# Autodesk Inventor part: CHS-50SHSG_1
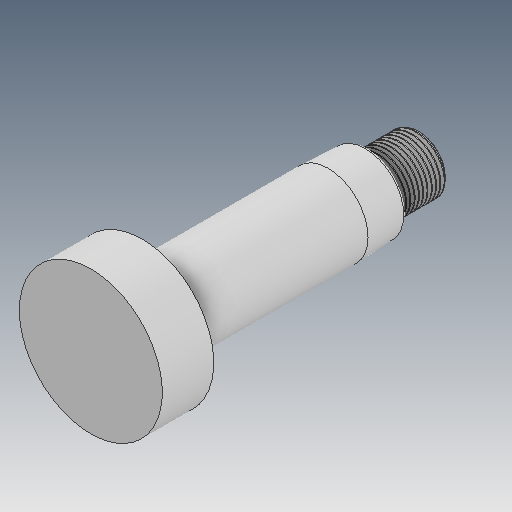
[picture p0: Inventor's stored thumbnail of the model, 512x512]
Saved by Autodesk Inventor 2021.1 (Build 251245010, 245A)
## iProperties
Created: 2019-04
Part Number: CHS-50SHSG_1
Material: Ogólny
Document SubType Name: Modeling
Designer: user
Density: 1 g/cm^3
Appearance: Domyślna
Author: user
Revision Number: ÈÎºÎ
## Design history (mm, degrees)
feature "ÊäÈë1"
node "Bryła1"
